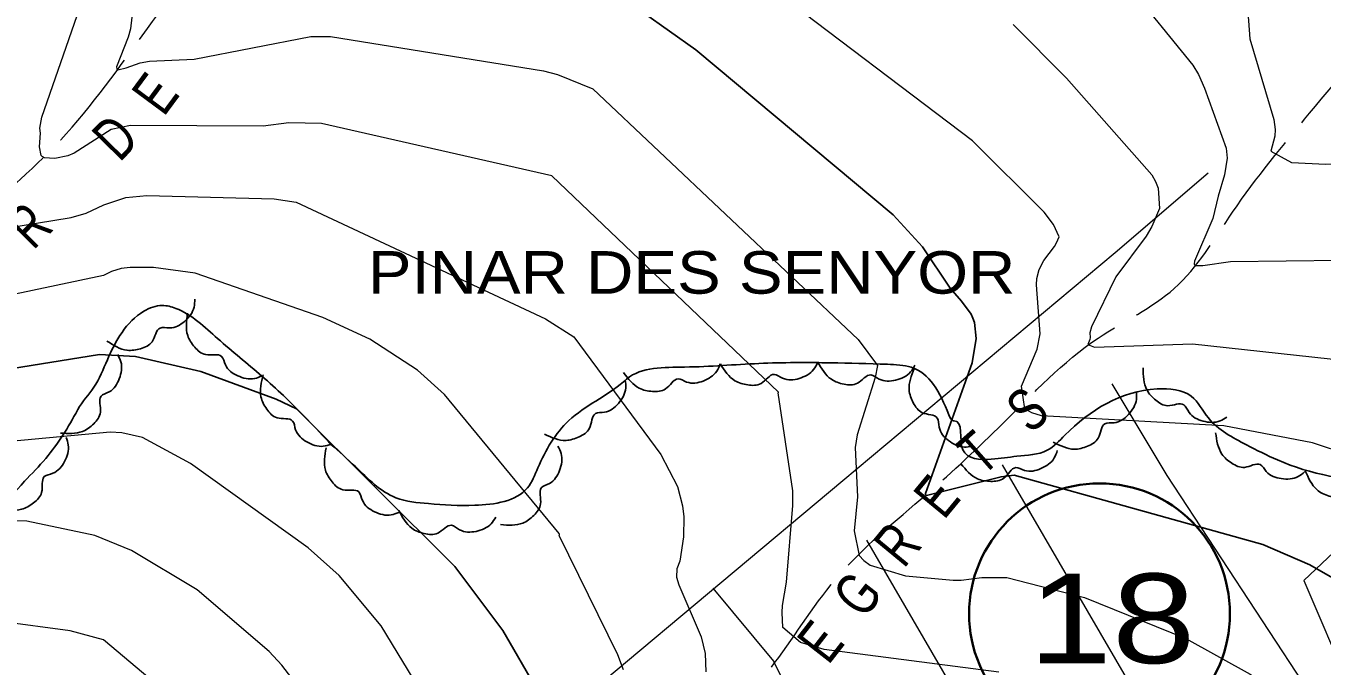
# Model space of a CAD drawing. Extents: x 483847 to 488453, y 4383581 to 4386795.
# Drawn here: x 485582.6 to 485871.9, y 4386191.5 to 4386334.4 of the extents above; entities that cross this region are included whole.
import ezdxf
from ezdxf.enums import TextEntityAlignment as Align

# ---------------------------------------------------------------- set-up
doc = ezdxf.new("R2010")
doc.units = 0
doc.header["$LTSCALE"] = 3.8
doc.linetypes.add('LONG_DASHED', pattern=[7.5, 6, -1.5])
for name, color, linetype, lineweight in [('13', 7, 'Continuous', 25), ('15', 7, 'LONG_DASHED', 13), ('27', 7, 'Continuous', 25), ('51', 7, 'Continuous', 13), ('6', 7, 'Continuous', 35), ('8', 7, 'Continuous', 25), ('9', 7, 'Continuous', 13)]:
    doc.layers.add(name, color=color, linetype=linetype, lineweight=lineweight)
doc.layers.add('5', color=7, linetype='Continuous')

msp = doc.modelspace()

# ---------------------------------------------------------------- linework, layer by layer
at = {"layer": '15'}
for points in [[(485505.12, 4386233.49), (485541.55, 4386262.3), (485570.61, 4386290.32), (485591.61, 4386310.36), (485610.88, 4386335.44), (485630.94, 4386363.52), (485648.13, 4386395.39), (485669.92, 4386429.59), (485677.83, 4386444.18)], [(485669.49, 4386110.7), (485685.13, 4386128.86), (485703.26, 4386142.48), (485721.48, 4386157.08), (485732.87, 4386172.22), (485748.75, 4386190.98), (485763.29, 4386210.88), (485783.67, 4386229.94), (485800.63, 4386245.68), (485821.91, 4386264.74), (485838.88, 4386275.82), (485851.88, 4386292.82), (485869.08, 4386314.93), (485890.07, 4386339.7), (485910.38, 4386364.39), (485923.72, 4386389.19)]]:
    msp.add_spline(points, degree=3, dxfattribs=at)
at = {"layer": '27'}
for points in [[(485978.1, 4386409.04), (485977.69, 4386401.47), (485977.49, 4386397.57), (485977.14, 4386388.87), (485977.44, 4386383.77), (485977.48, 4386375.66), (485974.93, 4386365.79), (485961.93, 4386359.08), (485960.27, 4386358.42), (485957.35, 4386353.29), (485952.49, 4386344.43), (485951.68, 4386339.86), (485952.03, 4386338.58), (485955.14, 4386335.31), (485956.08, 4386332.9), (485956.87, 4386330.19), (485957.57, 4386326.87), (485957.63, 4386325.6), (485955.45, 4386325.33), (485946.24, 4386332.44), (485941.62, 4386334.31), (485940.77, 4386332.89), (485941.08, 4386328.16), (485941.91, 4386317.79), (485941.97, 4386311.71), (485942.01, 4386304.44), (485941.77, 4386297.84), (485939.11, 4386295.25), (485931.55, 4386296.56), (485930.77, 4386299.64), (485929.9, 4386302.28), (485923.45, 4386302.53), (485916.02, 4386302.48), (485911.9, 4386302.47), (485912.01, 4386300.21), (485911.66, 4386296.39), (485909.25, 4386290.57), (485906.55, 4386285.06), (485904.62, 4386281.79), (485897.13, 4386282.19), (485894.28, 4386282.46), (485893.11, 4386279.4), (485890.79, 4386274.86), (485889.85, 4386271.64), (485890.31, 4386272.46), (485912.07, 4386256.62), (485918.29, 4386251.35), (485926.44, 4386243.73), (485928.55, 4386239.35), (485928.73, 4386235.89), (485927.36, 4386229.24), (485906.94, 4386244.24), (485900.68, 4386242.37), (485894.83, 4386237.43), (485890.72, 4386232.84), (485886.13, 4386232.38), (485861.89, 4386237.53), (485854.96, 4386240.93), (485846.5, 4386246.9), (485842.66, 4386251.76), (485835.03, 4386253.37), (485814.48, 4386243.08), (485810.53, 4386239.69), (485803.75, 4386238.36), (485798.04, 4386237.69), (485791.69, 4386239.81), (485789.69, 4386246.29), (485789.61, 4386246.29), (485788.58, 4386247.58), (485780.18, 4386258.21), (485774.86, 4386258.88), (485762.26, 4386259.22), (485746.2, 4386259.07), (485729.6, 4386258.26), (485716.66, 4386255.59), (485715.98, 4386255), (485703.77, 4386246.32), (485696.87, 4386235.77), (485694.55, 4386231.3), (485682.79, 4386227.41), (485672.44, 4386227.79), (485665.18, 4386229.09), (485656.13, 4386236.05), (485650.69, 4386241.01)], [(485650.69, 4386241.01), (485640.07, 4386251.89), (485630.36, 4386260.43), (485625.4, 4386264.63), (485616.04, 4386271.37), (485613.04, 4386272.01), (485608.9, 4386270.72), (485600.79, 4386259.88), (485597.78, 4386253.77), (485594.18, 4386248.79), (485594.1, 4386248.64), (485587.04, 4386237.87), (485582.32, 4386232.76), (485576.51, 4386225.56), (485572.65, 4386217.96), (485556.15, 4386197.64), (485542.65, 4386197.46), (485528.5, 4386200.14), (485519.88, 4386205.66), (485509.36, 4386210.39), (485509.02, 4386218.05), (485507.27, 4386221.68), (485503.59, 4386226.46), (485500.95, 4386241.2), (485503.59, 4386247.54), (485509.96, 4386257.58), (485514.75, 4386262.01), (485526.01, 4386272.36), (485533.83, 4386279.07), (485545.44, 4386288.28), (485558.02, 4386296.81), (485562.08, 4386302.08), (485567.49, 4386313.41), (485567.12, 4386323.92), (485558.79, 4386334.54), (485531.75, 4386342.96), (485505.59, 4386355.71), (485486.58, 4386364.31), (485481.5, 4386365.81), (485475.75, 4386367.7), (485455.69, 4386376.31), (485449.91, 4386379.7)], [(485620.28, 4386273.4), (485620.13, 4386271.63), (485618.02, 4386268.47), (485614.64, 4386266.99), (485612.59, 4386266.97), (485610.76, 4386263.92), (485608.21, 4386262.37), (485605.2, 4386262.03), (485600.69, 4386264.07)], [(485635.3, 4386256.3), (485633.63, 4386255.71), (485629.88, 4386256.32), (485627.13, 4386258.78), (485626.27, 4386260.65), (485622.73, 4386261.04), (485620.27, 4386262.73), (485618.71, 4386265.32), (485618.7, 4386270.28)], [(485603.1, 4386261.06), (485603.81, 4386259.44), (485603.45, 4386255.66), (485601.19, 4386252.74), (485599.39, 4386251.75), (485599.24, 4386248.2), (485597.73, 4386245.62), (485595.25, 4386243.89), (485590.3, 4386243.54)], [(485737.57, 4386258.99), (485736.81, 4386257.38), (485733.74, 4386255.15), (485730.06, 4386254.93), (485728.13, 4386255.63), (485725.36, 4386253.39), (485722.43, 4386252.83), (485719.49, 4386253.54), (485715.96, 4386257.03)], [(485759.28, 4386259.25), (485758.4, 4386257.71), (485755.17, 4386255.72), (485751.48, 4386255.78), (485749.61, 4386256.63), (485746.67, 4386254.62), (485743.71, 4386254.28), (485740.83, 4386255.22), (485737.58, 4386258.96)], [(485780.97, 4386258.67), (485780.02, 4386257.17), (485776.69, 4386255.34), (485773.01, 4386255.58), (485771.18, 4386256.52), (485768.15, 4386254.65), (485765.18, 4386254.45), (485762.35, 4386255.53), (485759.28, 4386259.43)], [(485793.8, 4386240.58), (485792.03, 4386240.39), (485788.53, 4386241.84), (485786.41, 4386244.86), (485786, 4386246.88), (485782.65, 4386248.07), (485780.64, 4386250.27), (485779.71, 4386253.15), (485780.84, 4386257.98)], [(485850.64, 4386247.09), (485849.09, 4386246.23), (485845.29, 4386246.2), (485842.17, 4386248.16), (485841, 4386249.85), (485837.45, 4386249.64), (485834.74, 4386250.88), (485832.76, 4386253.17), (485831.91, 4386258.06)], [(485650.69, 4386241.01), (485648.97, 4386240.59), (485645.3, 4386241.56), (485642.8, 4386244.28), (485642.13, 4386246.22), (485638.65, 4386246.96), (485636.36, 4386248.88), (485635.06, 4386251.61), (485635.54, 4386256.55)], [(485716.36, 4386255.37), (485716.47, 4386253.6), (485714.85, 4386250.17), (485711.73, 4386248.2), (485709.71, 4386247.88), (485708.35, 4386244.59), (485706.06, 4386242.68), (485703.14, 4386241.89), (485698.37, 4386243.25)], [(485830.4, 4386252.81), (485830.43, 4386251.03), (485828.66, 4386247.68), (485825.45, 4386245.85), (485823.41, 4386245.62), (485821.91, 4386242.4), (485819.53, 4386240.59), (485816.58, 4386239.93), (485811.88, 4386241.5)], [(485867.96, 4386234.86), (485866.52, 4386233.82), (485862.76, 4386233.36), (485859.42, 4386234.94), (485858.07, 4386236.49), (485854.57, 4386235.88), (485851.73, 4386236.8), (485849.5, 4386238.85), (485848.1, 4386243.6)], [(485591.57, 4386242.57), (485592.07, 4386240.87), (485591.24, 4386237.16), (485588.63, 4386234.56), (485586.72, 4386233.8), (485586.12, 4386230.29), (485584.31, 4386227.93), (485581.63, 4386226.52), (485576.68, 4386226.79)], [(485665.8, 4386225.81), (485664.11, 4386225.26), (485660.38, 4386225.97), (485657.7, 4386228.51), (485656.88, 4386230.39), (485653.36, 4386230.88), (485650.94, 4386232.63), (485649.46, 4386235.26), (485649.58, 4386240.22)], [(485701.35, 4386240.6), (485702.06, 4386238.97), (485701.7, 4386235.19), (485699.43, 4386232.28), (485697.63, 4386231.29), (485697.47, 4386227.74), (485695.96, 4386225.16), (485693.48, 4386223.43), (485688.53, 4386223.09)], [(485812.78, 4386239.61), (485812.1, 4386237.97), (485809.13, 4386235.6), (485805.46, 4386235.2), (485803.5, 4386235.81), (485800.84, 4386233.46), (485797.94, 4386232.75), (485794.97, 4386233.33), (485791.28, 4386236.65)], [(485889.58, 4386231.86), (485888.47, 4386230.48), (485884.96, 4386229.05), (485881.32, 4386229.7), (485879.61, 4386230.84), (485876.39, 4386229.33), (485873.41, 4386229.47), (485870.73, 4386230.86), (485868.12, 4386235.09)], [(485687.45, 4386224.76), (485686.44, 4386223.3), (485683.06, 4386221.59), (485679.38, 4386221.96), (485677.59, 4386222.95), (485674.5, 4386221.19), (485671.51, 4386221.1), (485668.73, 4386222.28), (485665.8, 4386226.28)]]:
    msp.add_spline(points, degree=3, dxfattribs=at)
at = {"layer": '51'}
for points in [[(485557.69, 4386053.4), (485619.2, 4386109.77), (485652.25, 4386138.03), (485680.76, 4386164.19), (485710.88, 4386187.69), (485764.88, 4386232.91), (485825.71, 4386283.82), (485846.45, 4386301.6)], [(485762.73, 4386103.36), (485776.92, 4386114.56), (485810.74, 4386139.14), (485844.25, 4386163.42), (485869.22, 4386182.95), (485869.47, 4386184.74), (485869.18, 4386185.42), (485837.31, 4386234.05), (485824.99, 4386254.49)], [(485800.5, 4386236.46), (485828.7, 4386188.03), (485842.84, 4386164.12)], [(485891.93, 4386233.49), (485867.81, 4386210.65), (485877.98, 4386186.8), (485901.59, 4386137.69)], [(485815.98, 4386143.72), (485789.07, 4386187.25), (485770.24, 4386219.63)], [(485735.88, 4386208.94), (485749.45, 4386192.62), (485756.3, 4386178.64), (485765.9, 4386162.14), (485780.14, 4386140.33)]]:
    msp.add_lwpolyline(points, dxfattribs=at)
at = {"layer": '6'}
msp.add_circle((485822.2, 4386203.2), 29.1, dxfattribs=at)
at = {"layer": '8'}
for points in [[(485885.11, 4386205), (485869.16, 4386214.13), (485858.62, 4386218.64), (485803.16, 4386234.15), (485800.22, 4386233.78), (485783.58, 4386229.61), (485783.44, 4386229.65), (485783.42, 4386229.67), (485783.4, 4386229.69), (485783.38, 4386229.79), (485783.39, 4386229.95), (485783.39, 4386230.03), (485793.76, 4386259.23), (485794.7, 4386264.61), (485794.26, 4386268.25), (485793.94, 4386269.18), (485793.55, 4386270.07), (485791.42, 4386272.98), (485788.86, 4386275.87), (485782.67, 4386285.13), (485776.18, 4386292.27), (485732.12, 4386329.05), (485720.33, 4386337.42)], [(485696.68, 4386186.23), (485689.04, 4386199.47), (485678.36, 4386213.78), (485642.98, 4386248.92), (485638.46, 4386251.08), (485621.65, 4386257.24), (485607.05, 4386260.64), (485599.02, 4386261.09), (485544.41, 4386252.27)]]:
    msp.add_lwpolyline(points, dxfattribs=at)
at = {"layer": '9'}
for points in [[(485812.13, 4386285.21), (485812.58, 4386285.97), (485813.17, 4386287.37), (485811.96, 4386290.13), (485809.86, 4386292.83), (485793.84, 4386308.77), (485748.22, 4386343.38)], [(485828.37, 4386343.72), (485842.99, 4386325.67), (485844.25, 4386323.6), (485845.64, 4386320.55), (485850.45, 4386307.12), (485850.65, 4386304.9), (485850.06, 4386301.21), (485848.65, 4386296.43), (485847.52, 4386291.4), (485843.36, 4386281.88), (485843.33, 4386281.31), (485843.46, 4386280.92), (485845.23, 4386280.94), (485851.39, 4386281.87), (485901.09, 4386282.43)], [(485854.99, 4386341.63), (485855.75, 4386331.55), (485861.06, 4386313.53), (485861.43, 4386311.33), (485861.29, 4386309.79), (485860.41, 4386306.44), (485865.05, 4386303.91), (485872.72, 4386303.53), (485930.13, 4386306.33), (485940.98, 4386305.22), (485948.2, 4386302.05), (485962.56, 4386292.33), (485971.79, 4386284.11), (485975.82, 4386279.5), (485985.79, 4386262.65), (485986.64, 4386261.48), (485991.92, 4386257.16), (485993.63, 4386254.98), (486004.66, 4386236.6), (486024.71, 4386213.41), (486027.78, 4386211.05), (486031.08, 4386209.21)], [(485606.6, 4386339.68), (485605.95, 4386333.81), (485605.4, 4386331.92), (485602.86, 4386325.28), (485602.91, 4386324.86), (485603.1, 4386324.61), (485604.97, 4386325.04), (485608.11, 4386326.21), (485610.16, 4386326.57), (485620.18, 4386327.02), (485646.19, 4386332.1), (485650.56, 4386332.03), (485698.08, 4386324.43), (485701.21, 4386323.6), (485709.13, 4386320.41), (485768.3, 4386264.41), (485772.62, 4386258.63), (485772.14, 4386255.92), (485768.1, 4386243.15), (485767.69, 4386240.3), (485768.22, 4386229.26), (485767.43, 4386221.68), (485768.53, 4386216.23), (485769.6, 4386215.07), (485771.01, 4386214.06), (485778.87, 4386211.66), (485789.54, 4386210.67), (485791.3, 4386210.67), (485795.95, 4386211.3)], [(485799.73, 4386190.19), (485760.76, 4386195.21), (485755.5, 4386196.79), (485751.56, 4386200.13), (485751.37, 4386203.47), (485751.43, 4386205.05), (485752.37, 4386210.24), (485753.79, 4386227.38), (485753.76, 4386230.66), (485750.49, 4386252.5), (485750.53, 4386252.6), (485750.53, 4386252.64), (485699.98, 4386300.93), (485648.56, 4386312.66), (485641.28, 4386312.78), (485635.54, 4386312.07), (485605.92, 4386312.22), (485601.62, 4386311.31), (485593.41, 4386306.05), (485591.96, 4386305.46), (485589.09, 4386304.8), (485586.72, 4386304.95), (485586.3, 4386305.19), (485585.98, 4386305.52), (485585.65, 4386307.44), (485585.87, 4386310.5), (485585.7, 4386311.63), (485586.14, 4386314.06), (485594.06, 4386336.74)], [(485802.92, 4386334.72), (485814.8, 4386322.76), (485833.84, 4386301.21), (485834.69, 4386299.69), (485835.31, 4386298.24), (485835.56, 4386293.66), (485833.86, 4386289.64), (485832.58, 4386287.46), (485825.82, 4386278.43), (485820.43, 4386267.25), (485820.06, 4386265.94), (485820.14, 4386264.87), (485820.05, 4386264.4), (485819.57, 4386263.27), (485821.11, 4386262.69), (485842.92, 4386263.45), (485900.98, 4386257.14)], [(485570.3, 4386288.04), (485592.74, 4386291.68), (485596.03, 4386292.6), (485600, 4386294.51), (485604.92, 4386296.1), (485609.58, 4386296.57), (485638.02, 4386295.86), (485642.92, 4386295.06), (485698.58, 4386269.04), (485704.9, 4386265.05), (485724.31, 4386238.76), (485728, 4386231.59), (485729.14, 4386227.28), (485729.43, 4386224.85), (485729.37, 4386220.36), (485728.54, 4386214.95), (485727.85, 4386213.2), (485727.76, 4386211.34), (485728.28, 4386209.62), (485733.27, 4386198.06), (485734.16, 4386194.31), (485734.31, 4386190.26)], [(485941.66, 4386181.09), (485940.14, 4386184.07), (485939.37, 4386186.02), (485936.24, 4386196.72), (485931.61, 4386206.36), (485926.94, 4386211.82), (485914.69, 4386221.91), (485898.85, 4386231.11), (485894.06, 4386233.3), (485869.71, 4386241.32), (485849.92, 4386245.17), (485809.25, 4386247.36), (485807.07, 4386248.04), (485805.5, 4386248.94), (485804.8, 4386253.98), (485808.3, 4386262.25), (485808.98, 4386265.7), (485808.14, 4386276.65), (485808.21, 4386278.06), (485808.71, 4386280.06), (485809.79, 4386282.08), (485812.13, 4386285.21)], [(485715.96, 4386190.65), (485714.7, 4386194.05), (485701.61, 4386220.65), (485701.62, 4386220.7), (485701.65, 4386220.83), (485701.65, 4386220.95), (485701.64, 4386221.01), (485701.61, 4386221.12), (485676.02, 4386252.16), (485669.99, 4386257.56), (485659.35, 4386264.49), (485648.85, 4386269.32), (485620.39, 4386279.21), (485611.09, 4386280.52), (485605.88, 4386280.47), (485603.84, 4386280.27), (485601.69, 4386279.57), (485599.95, 4386278.73), (485568.15, 4386272)], [(485676.36, 4386176.58), (485661.9, 4386200.49), (485652.51, 4386211.76), (485645.57, 4386217.9), (485619.34, 4386236.77), (485608.63, 4386242.51), (485603.98, 4386243.59), (485601.41, 4386243.74), (485545.57, 4386238.5)], [(485648.1, 4386180.75), (485639.74, 4386191.75), (485636.89, 4386194.77), (485620.83, 4386208.52), (485606.2, 4386217.35), (485597.96, 4386220.67), (485582.84, 4386223.84), (485500.88, 4386225.37)], [(485617.34, 4386182.75), (485599.9, 4386197.38), (485592.52, 4386199.36), (485499.15, 4386211.92)], [(485795.95, 4386211.3), (485801.5, 4386211.29), (485818.87, 4386206.81), (485841.44, 4386197.65), (485855.84, 4386189.7), (485875.93, 4386175.1), (485898.54, 4386150.6), (485903.05, 4386144.56), (485905.35, 4386140.37), (485905.66, 4386139.45), (485905.83, 4386138.63), (485905.23, 4386136.55), (485904.2, 4386135.12), (485904.09, 4386134.72), (485904.05, 4386134.31), (485904.55, 4386132.81), (485925.84, 4386082.54)]]:
    msp.add_lwpolyline(points, dxfattribs=at)

# ---------------------------------------------------------------- texts
at = {"layer": '13', "width": 1.25}
msp.add_text('18', height=20, dxfattribs=at).set_placement((485824.99, 4386192.16), align=Align.CENTER)
at = {"layer": '5', "width": 0.75}
for s, rotation, p in [('E', 53.53, (485615.26, 4386316.52)), ('D', 45.57, (485605.91, 4386306.29)), ('R', 45.57, (485586.66, 4386286.66)), ('S', 41.31, (485809.2, 4386245.27)), ('T', 41.31, (485798.16, 4386235.58)), ('E', 50.48, (485789.5, 4386226.42)), ('R', 50.48, (485780.71, 4386215.76)), ('G', 52.045, (485771.91, 4386204.69)), ('E', 52.045, (485763.63, 4386194.08))]:
    msp.add_text(s, height=9.49, rotation=rotation, dxfattribs=at).set_placement(p, align=Align.CENTER)
at = {"layer": '5', "width": 1.15}
msp.add_text('PINAR DES SENYOR', height=9.5, dxfattribs=at).set_placement((485803.42, 4386274.65), align=Align.RIGHT)

doc.saveas('drawing.dxf')
